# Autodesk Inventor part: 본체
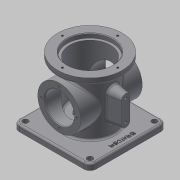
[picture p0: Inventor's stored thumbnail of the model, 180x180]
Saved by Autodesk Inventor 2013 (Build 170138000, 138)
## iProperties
Created: 2017-08
Part Number: 본체
Material: 일반
Document SubType Name: Modeling
Designer: mduedu
Density: 2.71 g/cm^3
Mass: 872.327 g
Surface Area: 642.238 cm^2
Volume: 321.892 cm^3
Author: mduedu
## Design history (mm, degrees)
sketch "스케치1"
  geometry: L1 (-62.5, -62.5)-(62.5, -62.5); L2 (62.5, -62.5)-(62.5, 62.5); L3 (62.5, 62.5)-(-62.5, 62.5); L4 (-62.5, 62.5)-(-62.5, -62.5); L5 (-62.5, -62.5)-(62.5, 62.5); L6 (62.5, -62.5)-(-62.5, 62.5); 1 further point
  constraints: 12 end point, 2 midpoint, 2 parallel, 1 horizontal, 1 perpendicular
  dimensions: "d232" = 125 distance of L3.end L2.end; "d233" = 125 distance of L2.end L1.end
extrude "돌출1" new body sketch "스케치1" distance "d5" = 10; taper "d6" = 0 deg
sketch "스케치2"
  geometry: C1 r 38 at (0, 0); 1 further point
  constraints: 1 centre point, 1 coincident
  dimensions: "d111" = 76 diameter of C1
extrude "돌출2" join sketch "스케치2" distance "d12" = 88; taper "d13" = 0 deg
sketch "스케치3"
  geometry: C1 r 52.5 at (0, 0); 1 further point
  constraints: 1 centre point, 1 coincident
  dimensions: "d114" = 105 diameter of C1
extrude "돌출3" join sketch "스케치3" distance "d19" = 10; taper "d20" = 0 deg
sketch "스케치4"
  geometry: C1 r 33 at (0, 0); 1 further point
  constraints: 1 centre point, 1 coincident
  dimensions: "d115" = 66 diameter of C1
extrude "돌출4" cut sketch "스케치4" distance "d26" = 86; taper "d27" = 0 deg
sketch "스케치5"
  geometry: C1 r 37 at (0, 0); 1 further point
  constraints: 1 centre point, 1 coincident
  dimensions: "d116" = 74 diameter of C1
extrude "돌출5" cut sketch "스케치5" distance "d29" = 7; taper "d30" = 0 deg
node "작업 평면1"
sketch "스케치18"
  geometry: L1 (-62.5, 0)-(62.5, 0) reference; C1 r 35 at (0, 54); 1 further point
  constraints: 1 centre point, 1 vertical alignment
  dimensions: "d118" = 70 diameter of C1; "d234" = 54 distance from line of C1.centre L1
extrude "돌출9" join sketch "스케치18" stored distance "d120" = 10; taper "d121" = 0 deg
hole "구멍8" diameter "d124" = 48; stored, may be unused: countersink angle "d128" = 90 deg, drill point angle "d130" = 118 deg; dims "d122" = 10, "d123" = 10, "d125" = 6, "d126" = 4, "d127" = 2, "d129" = 8
sketch "스케치9"
  geometry: C1 r 33 at (0, 0); 1 further point
  constraints: 1 centre point, 1 coincident
  dimensions: "d131" = 66 diameter of C1
extrude "돌출8" cut sketch "스케치9" distance "d43" = 16; taper "d44" = 0 deg
node "작업 평면2"
fillet "모깎기9" dims "d137" = 3
fillet "모깎기10" dims "d138" = 3
chamfer "모따기2" distance "d139" = 1; stored, may be unused: second distance "d140" = 2, angle "d141" = 45 deg
fillet "모깎기11" dims "d142" = 3
fillet "모깎기12" dims "d143" = 3
fillet "모깎기13" dims "d144" = 3
node "작업 평면3"
sketch "스케치20"
  geometry: L1 (108, -52.5)-(108, 52.5) reference; L2 (37, 7)-(71, 7); L3 (37, -7)-(71, -7); L4 (0, -33)-(0, 33) reference; A1 r 7 centre (37, 0) between (37, 7) and (37, -7); A2 r 7 centre (71, 0) between (71, 7) and (71, -7); 1 further point
  constraints: 4 end point, 4 point on circle, 3 tangent, 2 centre point, 2 horizontal alignment, 1 parallel, 1 perpendicular
  dimensions: "d203" = 14 diameter of A1; "d206" = 30 distance edge to line of A2 L1; "d207" = 48 dimension on A2 A1 (derived); "d236" = 30 distance edge to line of A1 L4
extrude "돌출10" join sketch "스케치20" stored distance "d152" = 10; taper "d153" = 10 deg
sketch "스케치21"
  geometry: C1 r 7 at (0, 71) reference; C2 r 7 at (0, 37) reference; 3 further points
  constraints: 2 coincident
hole "구멍12" sketch "스케치21" at (0, 71), (0, 37) diameter "d219" = 4.134; stored, may be unused: countersink angle "d223" = 90 deg, drill point angle "d225" = 118 deg; dims "d220" = 6, "d221" = 4, "d222" = 2, "d224" = 8
fillet "모깎기18" dims "d229" = 3
sketch "스케치23"
  geometry: C1 r 20 at (0, 0); 1 further point
  constraints: 1 centre point, 1 coincident
  dimensions: "d168" = 40 diameter of C1
extrude "돌출12" cut sketch "스케치23" stored distance "d169" = 148.25; taper "d170" = 0 deg
sketch "스케치28"
  geometry: L1 (62.5, -62.5)-(62.5, 62.5) reference; 2 further points
  constraints: 1 horizontal alignment, 1 other
  dimensions: "d238" = 10 distance from line of point (52.5, 0) L1
feature "엠보싱4" sketch "스케치28" dims "d239" = 0.5, "d240" = 0
sketch "스케치25" dims "d178" = 58
  geometry: C1 r 35 at (0, 0) reference; 3 further points
  constraints: 2 vertical alignment, 1 coincident, 2 other
hole "구멍10" sketch "스케치25" at (0, 29) diameter "d179" = 3.242; stored, may be unused: countersink angle "d183" = 90 deg, drill point angle "d185" = 118 deg; dims "d180" = 4, "d181" = 4, "d182" = 2, "d184" = 6
sketch "스케치26" dims "d189" = 90
  geometry: 3 further points
  constraints: 2 vertical alignment, 1 coincident, 2 other
hole "구멍11" sketch "스케치26" at (0, 45) diameter "d190" = 3.242; stored, may be unused: countersink angle "d194" = 90 deg, drill point angle "d196" = 118 deg; dims "d191" = 4, "d192" = 4, "d193" = 2, "d195" = 6
chamfer "모따기4" distance "d200" = 1; stored, may be unused: second distance "d201" = 2, angle "d202" = 45 deg
fillet "모깎기19" dims "d241" = 10
sketch "스케치29"
  geometry: A1 r 10 centre (-52.5, 52.5) between (-52.5, 62.5) and (-62.5, 52.5) reference; A2 r 10 centre (52.5, 52.5) between (62.5, 52.5) and (52.5, 62.5) reference; A3 r 10 centre (52.5, -52.5) between (52.5, -62.5) and (62.5, -52.5) reference; A4 r 10 centre (-52.5, -52.5) between (-62.5, -52.5) and (-52.5, -62.5) reference; 5 further points
  constraints: 4 coincident
hole "구멍13" sketch "스케치29" at (-52.5, 52.5), (52.5, 52.5), (52.5, -52.5), (-52.5, -52.5) diameter "d242" = 9; stored, may be unused: countersink angle "d246" = 90 deg, drill point angle "d248" = 118 deg; dims "d243" = 6, "d244" = 4, "d245" = 2, "d247" = 8
fillet "모깎기20" dims "d249" = 3
node "솔리드1"
mirror "대칭2"
pattern_circular "원형 패턴1" dims angle "d187" = 360 deg
mirror "대칭3"
pattern_circular "원형 패턴2" dims angle "d198" = 360 deg
other parameters: "d147" = 58
